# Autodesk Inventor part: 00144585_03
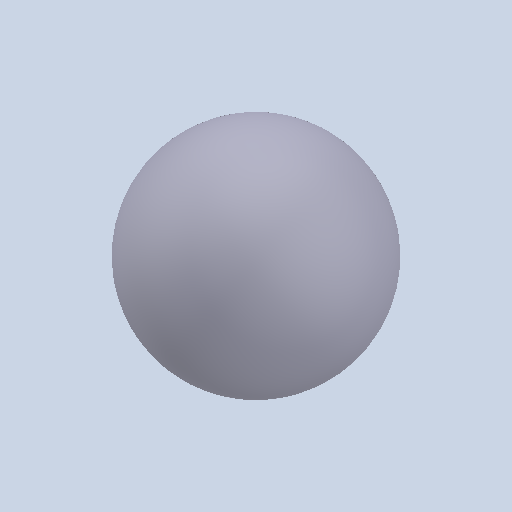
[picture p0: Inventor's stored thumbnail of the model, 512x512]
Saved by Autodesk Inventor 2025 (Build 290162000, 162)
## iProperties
Created: 2021-02
Part Number: 00144585_03
Material: Generico
Document SubType Name: Modeling
Designer: Ryzen5700u
Density: 1 g/cm^3
Appearance: Default
Author: Ryzen5700u
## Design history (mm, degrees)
feature "Solido1"
node "Solido2"
